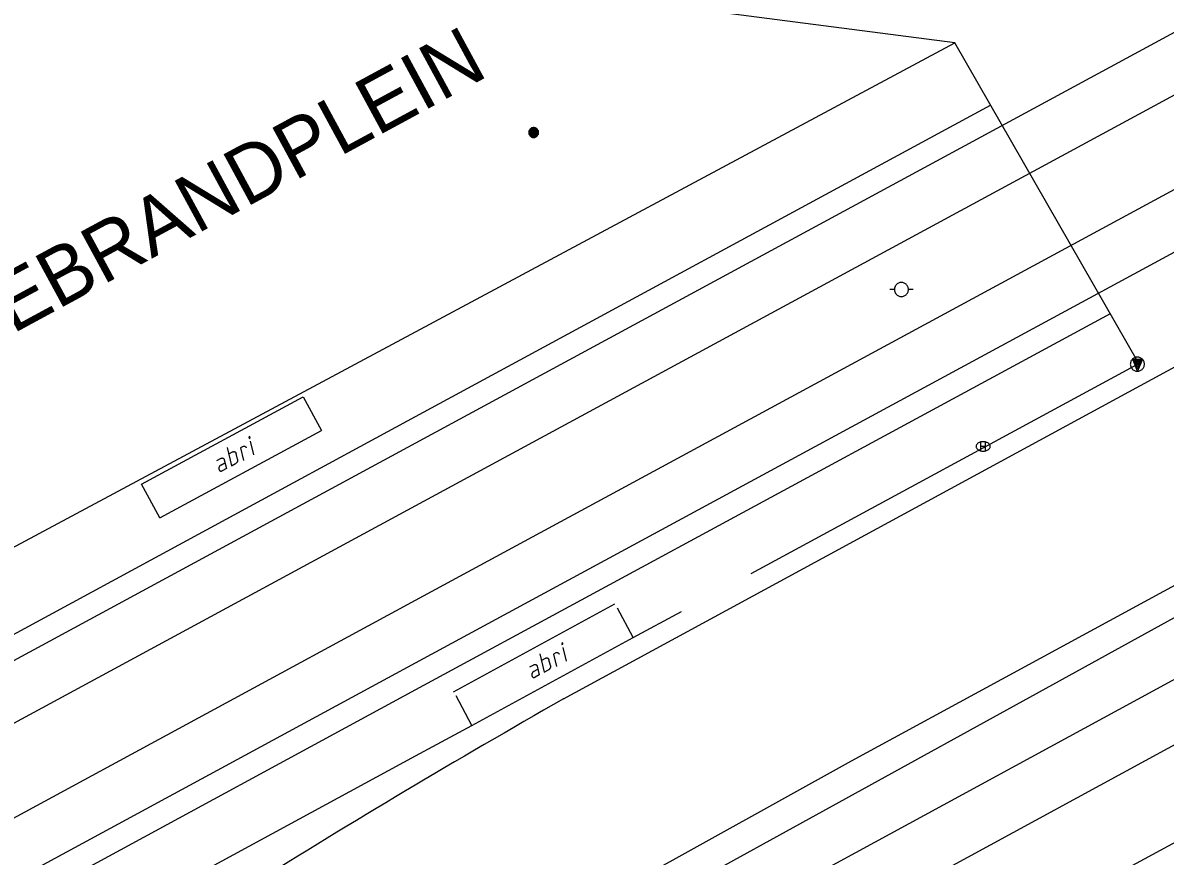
# Model space of a CAD drawing. Extents: x 81065 to 81486, y 452384 to 452681.
# Drawn here: x 81239.76 to 81269.54, y 452489.52 to 452511.24 of the extents above; entities that cross this region are included whole.
import ezdxf

# ---------------------------------------------------------------- set-up
doc = ezdxf.new("R2010")
doc.units = 0
for name, color, linetype in [('B-BH-AL-TOPOGRAFIE_STRAATNAAM-S', 7, 'Continuous'), ('B-BH-GR-BOOM-S', 7, 'Continuous'), ('B-BH-IE-MEUBILAIR-WEGMEUBILAIR-VERKEERSBORD-S', 7, 'Continuous'), ('B-BH-IE-MEUBILAIR_WEGMEUBILAIR_ABRI-S', 7, 'Continuous'), ('B-BH-IE-MEUBILAIR_WEGMEUBILAIR_TRAMMAST-S', 7, 'Continuous'), ('B-BH-OG-TOPOGRAFIE_BEBOUWING-GV', 7, 'Continuous'), ('B-BH-VH-KANTOPSLUITING-GV', 7, 'Continuous'), ('B-BH-VW-HALTEPAAL-S', 7, 'Continuous'), ('B-SB-OG-WEG_SPOOR_TRAM-G', 7, 'Continuous'), ('B-WE-VW-MARKERING_LANGS_STREEP_30270_010-G', 7, 'Continuous')]:
    doc.layers.add(name, color=color, linetype=linetype)

msp = doc.modelspace()

# ---------------------------------------------------------------- linework, layer by layer
at = {"layer": 'B-BH-GR-BOOM-S'}
for points in [[(81252.948, 452508.381), (81252.949, 452508.367), (81252.951, 452508.354), (81252.954, 452508.341), (81252.959, 452508.329), (81252.965, 452508.317), (81252.973, 452508.305), (81252.981, 452508.295), (81252.991, 452508.285), (81253.001, 452508.277), (81253.013, 452508.269), (81253.025, 452508.263), (81253.037, 452508.258), (81253.05, 452508.255), (81253.063, 452508.253), (81253.077, 452508.252), (81253.09, 452508.253), (81253.104, 452508.255), (81253.117, 452508.258), (81253.129, 452508.263), (81253.141, 452508.269), (81253.153, 452508.277), (81253.163, 452508.285), (81253.173, 452508.295), (81253.181, 452508.305), (81253.189, 452508.317), (81253.195, 452508.329), (81253.199, 452508.341), (81253.203, 452508.354), (81253.205, 452508.367), (81253.206, 452508.381), (81253.205, 452508.394), (81253.203, 452508.408), (81253.199, 452508.421), (81253.195, 452508.433), (81253.189, 452508.445), (81253.181, 452508.457), (81253.173, 452508.467), (81253.163, 452508.477), (81253.153, 452508.485), (81253.141, 452508.493), (81253.129, 452508.499), (81253.117, 452508.503), (81253.104, 452508.507), (81253.09, 452508.509), (81253.077, 452508.51), (81253.063, 452508.509), (81253.05, 452508.507), (81253.037, 452508.503), (81253.025, 452508.499), (81253.013, 452508.493), (81253.001, 452508.485), (81252.991, 452508.477), (81252.981, 452508.467), (81252.973, 452508.457), (81252.965, 452508.445), (81252.959, 452508.433), (81252.954, 452508.421), (81252.951, 452508.408), (81252.949, 452508.394), (81252.948, 452508.381)], [(81252.973, 452508.381), (81252.973, 452508.37), (81252.975, 452508.359), (81252.978, 452508.349), (81252.982, 452508.338), (81252.986, 452508.329), (81252.992, 452508.32), (81252.999, 452508.311), (81253.007, 452508.303), (81253.016, 452508.296), (81253.025, 452508.29), (81253.034, 452508.286), (81253.045, 452508.282), (81253.055, 452508.279), (81253.066, 452508.277), (81253.077, 452508.277), (81253.088, 452508.277), (81253.099, 452508.279), (81253.109, 452508.282), (81253.119, 452508.286), (81253.129, 452508.29), (81253.138, 452508.296), (81253.147, 452508.303), (81253.155, 452508.311), (81253.161, 452508.32), (81253.167, 452508.329), (81253.172, 452508.338), (81253.176, 452508.349), (81253.179, 452508.359), (81253.181, 452508.37), (81253.181, 452508.381), (81253.181, 452508.392), (81253.179, 452508.403), (81253.176, 452508.413), (81253.172, 452508.423), (81253.167, 452508.433), (81253.161, 452508.442), (81253.155, 452508.451), (81253.147, 452508.459), (81253.138, 452508.465), (81253.129, 452508.471), (81253.119, 452508.476), (81253.109, 452508.48), (81253.099, 452508.483), (81253.088, 452508.485), (81253.077, 452508.485), (81253.066, 452508.485), (81253.055, 452508.483), (81253.045, 452508.48), (81253.034, 452508.476), (81253.025, 452508.471), (81253.016, 452508.465), (81253.007, 452508.459), (81252.999, 452508.451), (81252.992, 452508.442), (81252.986, 452508.433), (81252.982, 452508.423), (81252.978, 452508.413), (81252.975, 452508.403), (81252.973, 452508.392), (81252.973, 452508.381)], [(81252.995, 452508.381), (81252.996, 452508.372), (81252.997, 452508.364), (81252.999, 452508.356), (81253.002, 452508.348), (81253.006, 452508.34), (81253.011, 452508.333), (81253.016, 452508.326), (81253.022, 452508.32), (81253.029, 452508.315), (81253.036, 452508.31), (81253.044, 452508.306), (81253.052, 452508.303), (81253.06, 452508.301), (81253.068, 452508.3), (81253.077, 452508.299), (81253.085, 452508.3), (81253.094, 452508.301), (81253.102, 452508.303), (81253.11, 452508.306), (81253.118, 452508.31), (81253.125, 452508.315), (81253.132, 452508.32), (81253.138, 452508.326), (81253.143, 452508.333), (81253.148, 452508.34), (81253.151, 452508.348), (81253.155, 452508.356), (81253.157, 452508.364), (81253.158, 452508.372), (81253.159, 452508.381), (81253.158, 452508.389), (81253.157, 452508.398), (81253.155, 452508.406), (81253.151, 452508.414), (81253.148, 452508.422), (81253.143, 452508.429), (81253.138, 452508.436), (81253.132, 452508.442), (81253.125, 452508.447), (81253.118, 452508.452), (81253.11, 452508.455), (81253.102, 452508.459), (81253.094, 452508.461), (81253.085, 452508.462), (81253.077, 452508.463), (81253.068, 452508.462), (81253.06, 452508.461), (81253.052, 452508.459), (81253.044, 452508.455), (81253.036, 452508.452), (81253.029, 452508.447), (81253.022, 452508.442), (81253.016, 452508.436), (81253.011, 452508.429), (81253.006, 452508.422), (81253.002, 452508.414), (81252.999, 452508.406), (81252.997, 452508.398), (81252.996, 452508.389), (81252.995, 452508.381)], [(81253.018, 452508.381), (81253.019, 452508.375), (81253.02, 452508.369), (81253.021, 452508.363), (81253.023, 452508.357), (81253.026, 452508.352), (81253.03, 452508.346), (81253.033, 452508.342), (81253.038, 452508.337), (81253.042, 452508.334), (81253.048, 452508.33), (81253.053, 452508.327), (81253.059, 452508.325), (81253.065, 452508.324), (81253.071, 452508.323), (81253.077, 452508.322), (81253.083, 452508.323), (81253.089, 452508.324), (81253.095, 452508.325), (81253.101, 452508.327), (81253.106, 452508.33), (81253.111, 452508.334), (81253.116, 452508.337), (81253.121, 452508.342), (81253.124, 452508.346), (81253.128, 452508.352), (81253.131, 452508.357), (81253.133, 452508.363), (81253.134, 452508.369), (81253.135, 452508.375), (81253.136, 452508.381), (81253.135, 452508.387), (81253.134, 452508.393), (81253.133, 452508.399), (81253.131, 452508.405), (81253.128, 452508.41), (81253.124, 452508.415), (81253.121, 452508.42), (81253.116, 452508.425), (81253.111, 452508.428), (81253.106, 452508.432), (81253.101, 452508.435), (81253.095, 452508.437), (81253.089, 452508.438), (81253.083, 452508.439), (81253.077, 452508.44), (81253.071, 452508.439), (81253.065, 452508.438), (81253.059, 452508.437), (81253.053, 452508.435), (81253.048, 452508.432), (81253.042, 452508.428), (81253.038, 452508.425), (81253.033, 452508.42), (81253.03, 452508.415), (81253.026, 452508.41), (81253.023, 452508.405), (81253.021, 452508.399), (81253.02, 452508.393), (81253.019, 452508.387), (81253.018, 452508.381)], [(81253.041, 452508.381), (81253.041, 452508.377), (81253.042, 452508.374), (81253.043, 452508.37), (81253.044, 452508.366), (81253.046, 452508.363), (81253.048, 452508.36), (81253.05, 452508.357), (81253.053, 452508.354), (81253.056, 452508.352), (81253.059, 452508.35), (81253.062, 452508.348), (81253.066, 452508.347), (81253.07, 452508.346), (81253.073, 452508.345), (81253.077, 452508.345), (81253.081, 452508.345), (81253.084, 452508.346), (81253.088, 452508.347), (81253.092, 452508.348), (81253.095, 452508.35), (81253.098, 452508.352), (81253.101, 452508.354), (81253.103, 452508.357), (81253.106, 452508.36), (81253.108, 452508.363), (81253.11, 452508.366), (81253.111, 452508.37), (81253.112, 452508.374), (81253.113, 452508.377), (81253.113, 452508.381), (81253.113, 452508.385), (81253.112, 452508.388), (81253.111, 452508.392), (81253.11, 452508.396), (81253.108, 452508.399), (81253.106, 452508.402), (81253.103, 452508.405), (81253.101, 452508.407), (81253.098, 452508.41), (81253.095, 452508.412), (81253.092, 452508.414), (81253.088, 452508.415), (81253.084, 452508.416), (81253.081, 452508.417), (81253.077, 452508.417), (81253.073, 452508.417), (81253.07, 452508.416), (81253.066, 452508.415), (81253.062, 452508.414), (81253.059, 452508.412), (81253.056, 452508.41), (81253.053, 452508.407), (81253.05, 452508.405), (81253.048, 452508.402), (81253.046, 452508.399), (81253.044, 452508.396), (81253.043, 452508.392), (81253.042, 452508.388), (81253.041, 452508.385), (81253.041, 452508.381)], [(81253.064, 452508.381), (81253.064, 452508.38), (81253.064, 452508.378), (81253.065, 452508.377), (81253.065, 452508.376), (81253.066, 452508.375), (81253.067, 452508.373), (81253.067, 452508.372), (81253.068, 452508.371), (81253.069, 452508.371), (81253.071, 452508.37), (81253.072, 452508.369), (81253.073, 452508.369), (81253.074, 452508.368), (81253.076, 452508.368), (81253.077, 452508.368), (81253.078, 452508.368), (81253.08, 452508.368), (81253.081, 452508.369), (81253.082, 452508.369), (81253.083, 452508.37), (81253.085, 452508.371), (81253.086, 452508.371), (81253.087, 452508.372), (81253.087, 452508.373), (81253.088, 452508.375), (81253.089, 452508.376), (81253.089, 452508.377), (81253.09, 452508.378), (81253.09, 452508.38), (81253.09, 452508.381), (81253.09, 452508.382), (81253.09, 452508.384), (81253.089, 452508.385), (81253.089, 452508.386), (81253.088, 452508.387), (81253.087, 452508.389), (81253.087, 452508.39), (81253.086, 452508.391), (81253.085, 452508.391), (81253.083, 452508.392), (81253.082, 452508.393), (81253.081, 452508.393), (81253.08, 452508.394), (81253.078, 452508.394), (81253.077, 452508.394), (81253.076, 452508.394), (81253.074, 452508.394), (81253.073, 452508.393), (81253.072, 452508.393), (81253.071, 452508.392), (81253.069, 452508.391), (81253.068, 452508.391), (81253.067, 452508.39), (81253.067, 452508.389), (81253.066, 452508.387), (81253.065, 452508.386), (81253.065, 452508.385), (81253.064, 452508.384), (81253.064, 452508.382), (81253.064, 452508.381)]]:
    msp.add_lwpolyline(points, dxfattribs=at)
at = {"layer": 'B-BH-IE-MEUBILAIR-WEGMEUBILAIR-VERKEERSBORD-S'}
for p, q in [((81268.678, 452502.471), (81268.943, 452502.471)), ((81268.811, 452502.162), (81268.7, 452502.453)), ((81268.7, 452502.453), (81268.916, 452502.453)), ((81268.727, 452502.435), (81268.888, 452502.435)), ((81268.812, 452502.211), (81268.727, 452502.435)), ((81268.813, 452502.26), (81268.753, 452502.416)), ((81268.753, 452502.416), (81268.86, 452502.416)), ((81268.814, 452502.309), (81268.78, 452502.398)), ((81268.78, 452502.398), (81268.832, 452502.398)), ((81268.815, 452502.357), (81268.806, 452502.38)), ((81268.943, 452502.471), (81268.811, 452502.162)), ((81268.916, 452502.453), (81268.812, 452502.211)), ((81268.888, 452502.435), (81268.813, 452502.26)), ((81268.86, 452502.416), (81268.814, 452502.309)), ((81268.832, 452502.398), (81268.815, 452502.357))]:
    msp.add_line(p, q, dxfattribs=at)
msp.add_lwpolyline([(81268.628, 452502.345), (81268.629, 452502.326), (81268.632, 452502.307), (81268.637, 452502.288), (81268.644, 452502.27), (81268.652, 452502.253), (81268.663, 452502.237), (81268.675, 452502.222), (81268.688, 452502.209), (81268.703, 452502.197), (81268.719, 452502.186), (81268.736, 452502.178), (81268.754, 452502.171), (81268.773, 452502.166), (81268.792, 452502.163), (81268.811, 452502.162), (81268.83, 452502.163), (81268.849, 452502.166), (81268.868, 452502.171), (81268.885, 452502.178), (81268.902, 452502.186), (81268.919, 452502.197), (81268.933, 452502.209), (81268.947, 452502.222), (81268.959, 452502.237), (81268.969, 452502.253), (81268.978, 452502.27), (81268.985, 452502.288), (81268.99, 452502.307), (81268.993, 452502.326), (81268.994, 452502.345), (81268.993, 452502.364), (81268.99, 452502.383), (81268.985, 452502.402), (81268.978, 452502.419), (81268.969, 452502.436), (81268.959, 452502.453), (81268.947, 452502.467), (81268.933, 452502.481), (81268.919, 452502.493), (81268.902, 452502.503), (81268.885, 452502.512), (81268.868, 452502.519), (81268.849, 452502.524), (81268.83, 452502.527), (81268.811, 452502.528), (81268.792, 452502.527), (81268.773, 452502.524), (81268.754, 452502.519), (81268.736, 452502.512), (81268.719, 452502.503), (81268.703, 452502.493), (81268.688, 452502.481), (81268.675, 452502.467), (81268.663, 452502.453), (81268.652, 452502.436), (81268.644, 452502.419), (81268.637, 452502.402), (81268.632, 452502.383), (81268.629, 452502.364), (81268.628, 452502.345)], dxfattribs=at)
at = {"layer": 'B-BH-IE-MEUBILAIR_WEGMEUBILAIR_ABRI-S'}
for p, q in [((81243.331, 452498.336), (81247.548, 452500.613)), ((81245.78, 452499.981), (81245.697, 452500.334)), ((81245.238, 452500.057), (81245.128, 452499.998)), ((81245.358, 452499.867), (81245.322, 452500.018)), ((81244.82, 452499.832), (81244.93, 452499.891)), ((81244.922, 452499.716), (81245.032, 452499.776)), ((81250.988, 452493.809), (81255.192, 452496.096)), ((81255.67, 452495.218), (81255.261, 452495.984)), ((81251.466, 452492.931), (81255.67, 452495.218)), ((81253.934, 452494.605), (81253.85, 452494.958)), ((81253.392, 452494.68), (81253.282, 452494.621)), ((81253.513, 452494.49), (81253.476, 452494.641)), ((81252.975, 452494.453), (81253.085, 452494.513)), ((81253.077, 452494.338), (81253.187, 452494.398)), ((81251.466, 452492.931), (81251.057, 452493.697))]:
    msp.add_line(p, q, dxfattribs=at)
for points in [[(81243.331, 452498.336), (81242.856, 452499.216), (81247.073, 452501.493), (81247.548, 452500.613)], [(81245.089, 452500.176), (81245.2, 452499.696), (81245.31, 452499.756)], [(81245.239, 452500.058), (81245.246, 452500.061), (81245.253, 452500.064), (81245.26, 452500.065), (81245.267, 452500.066), (81245.275, 452500.066), (81245.281, 452500.064), (81245.288, 452500.062), (81245.294, 452500.06), (81245.3, 452500.056), (81245.305, 452500.051), (81245.31, 452500.046), (81245.314, 452500.04), (81245.318, 452500.033), (81245.321, 452500.026), (81245.323, 452500.018)], [(81245.502, 452500.2), (81245.436, 452500.164), (81245.516, 452499.838)], [(81245.503, 452500.201), (81245.51, 452500.204), (81245.517, 452500.206), (81245.524, 452500.208), (81245.531, 452500.208), (81245.538, 452500.208), (81245.545, 452500.207), (81245.552, 452500.205), (81245.558, 452500.202), (81245.564, 452500.198), (81245.569, 452500.194), (81245.574, 452500.188), (81245.578, 452500.182), (81245.582, 452500.176), (81245.585, 452500.168), (81245.587, 452500.161)], [(81244.923, 452499.717), (81244.916, 452499.713), (81244.91, 452499.708), (81244.903, 452499.702), (81244.898, 452499.696), (81244.892, 452499.689), (81244.888, 452499.681), (81244.883, 452499.674), (81244.88, 452499.665), (81244.877, 452499.657), (81244.875, 452499.648), (81244.873, 452499.639), (81244.873, 452499.631), (81244.873, 452499.622), (81244.873, 452499.614), (81244.875, 452499.606), (81244.877, 452499.598), (81244.88, 452499.591), (81244.884, 452499.584), (81244.888, 452499.578), (81244.893, 452499.573), (81244.898, 452499.568), (81244.904, 452499.564), (81244.91, 452499.561), (81244.917, 452499.559), (81244.923, 452499.558), (81244.93, 452499.558), (81244.938, 452499.558), (81244.945, 452499.56), (81244.952, 452499.562), (81244.959, 452499.566)], [(81244.931, 452499.892), (81244.938, 452499.895), (81244.945, 452499.897), (81244.952, 452499.899), (81244.959, 452499.9), (81244.966, 452499.899), (81244.973, 452499.898), (81244.98, 452499.896), (81244.986, 452499.893), (81244.992, 452499.889), (81244.997, 452499.885), (81245.002, 452499.879), (81245.006, 452499.873), (81245.01, 452499.867), (81245.013, 452499.859), (81245.015, 452499.852)], [(81245.014, 452499.851), (81245.068, 452499.625), (81244.958, 452499.565)], [(81245.359, 452499.867), (81245.36, 452499.859), (81245.361, 452499.851), (81245.361, 452499.842), (81245.361, 452499.833), (81245.359, 452499.824), (81245.357, 452499.816), (81245.354, 452499.807), (81245.35, 452499.799), (81245.346, 452499.791), (81245.341, 452499.784), (81245.336, 452499.777), (81245.33, 452499.771), (81245.324, 452499.765), (81245.318, 452499.76), (81245.311, 452499.756)], [(81253.242, 452494.798), (81253.355, 452494.319), (81253.465, 452494.379)], [(81253.393, 452494.681), (81253.4, 452494.684), (81253.407, 452494.687), (81253.414, 452494.688), (81253.421, 452494.689), (81253.428, 452494.689), (81253.435, 452494.687), (81253.442, 452494.685), (81253.448, 452494.682), (81253.454, 452494.679), (81253.459, 452494.674), (81253.464, 452494.669), (81253.468, 452494.663), (81253.472, 452494.656), (81253.475, 452494.649), (81253.477, 452494.641)], [(81253.656, 452494.824), (81253.59, 452494.788), (81253.67, 452494.462)], [(81253.657, 452494.824), (81253.664, 452494.827), (81253.671, 452494.83), (81253.678, 452494.832), (81253.685, 452494.832), (81253.692, 452494.832), (81253.699, 452494.831), (81253.705, 452494.829), (81253.711, 452494.826), (81253.717, 452494.822), (81253.723, 452494.817), (81253.728, 452494.812), (81253.732, 452494.806), (81253.735, 452494.799), (81253.738, 452494.792), (81253.741, 452494.784)], [(81253.078, 452494.339), (81253.071, 452494.334), (81253.065, 452494.33), (81253.059, 452494.324), (81253.053, 452494.317), (81253.047, 452494.311), (81253.043, 452494.303), (81253.039, 452494.295), (81253.035, 452494.287), (81253.032, 452494.278), (81253.03, 452494.27), (81253.029, 452494.261), (81253.028, 452494.252), (81253.028, 452494.244), (81253.029, 452494.235), (81253.03, 452494.227), (81253.033, 452494.22), (81253.035, 452494.212), (81253.039, 452494.206), (81253.043, 452494.2), (81253.048, 452494.194), (81253.054, 452494.19), (81253.059, 452494.186), (81253.066, 452494.183), (81253.072, 452494.181), (81253.079, 452494.18), (81253.086, 452494.18), (81253.093, 452494.18), (81253.1, 452494.182), (81253.107, 452494.184), (81253.114, 452494.188)], [(81253.085, 452494.513), (81253.093, 452494.517), (81253.1, 452494.519), (81253.107, 452494.521), (81253.114, 452494.522), (81253.121, 452494.521), (81253.128, 452494.52), (81253.134, 452494.518), (81253.141, 452494.515), (81253.146, 452494.511), (81253.152, 452494.507), (81253.157, 452494.501), (81253.161, 452494.495), (81253.164, 452494.489), (81253.167, 452494.482), (81253.17, 452494.474)], [(81253.169, 452494.473), (81253.224, 452494.247), (81253.114, 452494.187)], [(81253.513, 452494.49), (81253.515, 452494.482), (81253.516, 452494.474), (81253.516, 452494.465), (81253.515, 452494.456), (81253.514, 452494.448), (81253.512, 452494.439), (81253.509, 452494.43), (81253.505, 452494.422), (81253.501, 452494.414), (81253.496, 452494.407), (81253.491, 452494.4), (81253.485, 452494.394), (81253.479, 452494.388), (81253.473, 452494.383), (81253.466, 452494.379)]]:
    msp.add_lwpolyline(points, dxfattribs=at)
for points in [[(81245.661, 452500.411), (81245.687, 452500.425), (81245.682, 452500.456), (81245.655, 452500.442)], [(81253.814, 452495.035), (81253.84, 452495.049), (81253.835, 452495.08), (81253.808, 452495.066)]]:
    msp.add_lwpolyline(points, close=True, dxfattribs=at)
at = {"layer": 'B-BH-IE-MEUBILAIR_WEGMEUBILAIR_TRAMMAST-S'}
for p, q in [((81262.479, 452504.29), (81262.357, 452504.29)), ((81262.967, 452504.29), (81262.845, 452504.29))]:
    msp.add_line(p, q, dxfattribs=at)
msp.add_lwpolyline([(81262.479, 452504.29), (81262.48, 452504.271), (81262.483, 452504.252), (81262.488, 452504.233), (81262.495, 452504.215), (81262.503, 452504.198), (81262.514, 452504.182), (81262.526, 452504.167), (81262.539, 452504.154), (81262.554, 452504.142), (81262.57, 452504.131), (81262.587, 452504.123), (81262.605, 452504.116), (81262.624, 452504.111), (81262.643, 452504.108), (81262.662, 452504.107), (81262.681, 452504.108), (81262.7, 452504.111), (81262.719, 452504.116), (81262.736, 452504.123), (81262.753, 452504.131), (81262.77, 452504.142), (81262.784, 452504.154), (81262.798, 452504.167), (81262.81, 452504.182), (81262.82, 452504.198), (81262.829, 452504.215), (81262.836, 452504.233), (81262.841, 452504.252), (81262.844, 452504.271), (81262.845, 452504.29), (81262.844, 452504.309), (81262.841, 452504.328), (81262.836, 452504.347), (81262.829, 452504.364), (81262.82, 452504.381), (81262.81, 452504.398), (81262.798, 452504.412), (81262.784, 452504.426), (81262.77, 452504.438), (81262.753, 452504.448), (81262.736, 452504.457), (81262.719, 452504.464), (81262.7, 452504.469), (81262.681, 452504.472), (81262.662, 452504.473), (81262.643, 452504.472), (81262.624, 452504.469), (81262.605, 452504.464), (81262.587, 452504.457), (81262.57, 452504.448), (81262.554, 452504.438), (81262.539, 452504.426), (81262.526, 452504.412), (81262.514, 452504.398), (81262.503, 452504.381), (81262.495, 452504.364), (81262.488, 452504.347), (81262.483, 452504.328), (81262.48, 452504.309), (81262.479, 452504.29)], dxfattribs=at)
at = {"layer": 'B-BH-OG-TOPOGRAFIE_BEBOUWING-GV'}
msp.add_lwpolyline([(81259.141, 452474.46), (81255.077, 452481.918), (81257.035, 452482.985), (81256.613, 452483.737), (81261.697, 452486.487), (81262.103, 452485.714), (81274.44, 452492.398), (81274.017, 452493.17), (81279.096, 452495.951), (81279.515, 452495.177), (81281.473, 452496.234), (81285.665, 452488.523)], dxfattribs=at)
at = {"layer": 'B-BH-VH-KANTOPSLUITING-GV'}
for p, q in [((81232.312, 452493.712), (81264.058, 452510.715)), ((81250, 452500.979), (81264.986, 452509.098)), ((81268.105, 452503.66), (81250, 452493.854)), ((81261.363, 452492.008), (81282.776, 452503.64)), ((81254.451, 452487.309), (81283.281, 452503.175)), ((81253.855, 452493.619), (81270.515, 452502.67)), ((81258.749, 452496.887), (81268.85, 452502.361)), ((81233.291, 452491.927), (81250, 452500.979)), ((81255.064, 452484.432), (81284.809, 452500.591)), ((81255.67, 452495.218), (81256.931, 452495.901)), ((81250, 452493.854), (81236.189, 452486.374)), ((81250, 452492.137), (81251.466, 452492.931)), ((81236.906, 452485.042), (81250, 452492.137)), ((81253.769, 452487.801), (81261.363, 452492.008))]:
    msp.add_line(p, q, dxfattribs=at)
for points in [[(81264.058, 452510.715), (81241.105, 452513.698)], [(81268.85, 452502.361), (81264.058, 452510.715), (81264.034, 452510.719)]]:
    msp.add_lwpolyline(points, dxfattribs=at)
for centre, radius, start, end in [((81242.762, 452507.028), 9.811, 80.0525, 169.5766), ((81364.383, 452298.915), 223.889, 119.58237, 124.46006)]:
    msp.add_arc(centre, radius, start, end, dxfattribs=at)
at = {"layer": 'B-BH-VW-HALTEPAAL-S'}
for p, q in [((81264.731, 452500.086), (81264.731, 452500.316)), ((81264.853, 452500.086), (81264.853, 452500.316)), ((81264.853, 452500.201), (81264.731, 452500.201))]:
    msp.add_line(p, q, dxfattribs=at)
msp.add_lwpolyline([(81264.609, 452500.201), (81264.61, 452500.188), (81264.613, 452500.175), (81264.618, 452500.163), (81264.625, 452500.151), (81264.633, 452500.14), (81264.644, 452500.129), (81264.656, 452500.119), (81264.669, 452500.11), (81264.684, 452500.102), (81264.7, 452500.095), (81264.717, 452500.089), (81264.735, 452500.085), (81264.754, 452500.081), (81264.773, 452500.08), (81264.792, 452500.079), (81264.811, 452500.08), (81264.83, 452500.081), (81264.849, 452500.085), (81264.866, 452500.089), (81264.883, 452500.095), (81264.9, 452500.102), (81264.914, 452500.11), (81264.928, 452500.119), (81264.94, 452500.129), (81264.95, 452500.14), (81264.959, 452500.151), (81264.966, 452500.163), (81264.971, 452500.175), (81264.974, 452500.188), (81264.975, 452500.201), (81264.974, 452500.214), (81264.971, 452500.226), (81264.966, 452500.239), (81264.959, 452500.251), (81264.95, 452500.262), (81264.94, 452500.273), (81264.928, 452500.283), (81264.914, 452500.292), (81264.9, 452500.3), (81264.883, 452500.307), (81264.866, 452500.312), (81264.849, 452500.317), (81264.83, 452500.32), (81264.811, 452500.322), (81264.792, 452500.323), (81264.773, 452500.322), (81264.754, 452500.32), (81264.735, 452500.317), (81264.717, 452500.312), (81264.7, 452500.307), (81264.684, 452500.3), (81264.669, 452500.292), (81264.656, 452500.283), (81264.644, 452500.273), (81264.633, 452500.262), (81264.625, 452500.251), (81264.618, 452500.239), (81264.613, 452500.226), (81264.61, 452500.214), (81264.609, 452500.201)], dxfattribs=at)
at = {"layer": 'B-SB-OG-WEG_SPOOR_TRAM-G'}
for p, q in [((81288.285, 452521.011), (81250, 452500.286)), ((81288.969, 452519.749), (81250, 452498.654)), ((81250, 452496.192), (81288.558, 452517.065)), ((81250, 452494.56), (81289.242, 452515.803)), ((81250, 452500.286), (81195.496, 452470.783)), ((81250, 452498.654), (81196.18, 452469.521)), ((81198.781, 452468.467), (81250, 452496.192)), ((81199.465, 452467.205), (81250, 452494.56))]:
    msp.add_line(p, q, dxfattribs=at)
at = {"layer": 'B-WE-VW-MARKERING_LANGS_STREEP_30270_010-G'}
msp.add_line((81283.619, 452501.652), (81255.207, 452486.216), dxfattribs=at)

# ---------------------------------------------------------------- texts
at = {"layer": 'B-BH-AL-TOPOGRAFIE_STRAATNAAM-S'}
msp.add_text('HILDEBRANDPLEIN', height=1.5, rotation=28.4741, dxfattribs=at).set_placement((81235.475, 452500.944))

doc.saveas('drawing.dxf')
